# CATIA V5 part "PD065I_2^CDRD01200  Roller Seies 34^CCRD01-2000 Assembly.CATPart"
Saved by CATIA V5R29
Part number: PD065I_2^CDRD01200  Roller Seies 34^CCRD01-2000 Assembly
Definition: PD065I_2
Nomenclature: PD065I_Sprocket
Source: Unknown
Bounding box of the stored display mesh (mm): x -24.678 to 24.678, y -42 to 0, z -24.678 to 24.678
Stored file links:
  C:\가치같이\SmartFactory_BoxErectorConveyor\PD065I_2^CDRD01200  Roller Seies 34^CCRD01-2000 Assembly.CATPart
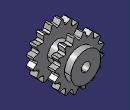
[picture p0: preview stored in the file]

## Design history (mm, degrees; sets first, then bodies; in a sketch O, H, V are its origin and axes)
Body1 "Cut-Extrude40" (main body)
  Solid1: solid without history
